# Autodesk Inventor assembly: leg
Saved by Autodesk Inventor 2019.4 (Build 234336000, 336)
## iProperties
Created: 2020-09
Part Number: leg
Document SubType Name: Assembly
Designer: Administrator
Title: leg
Author: Administrator
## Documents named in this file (5)
- c:\worker\convert-fusion-r07\tmp\job-1\164\output\files\c50c4620-2026-4653-9277-f8972be5ac5a\leg_3.iam
- c:\worker\convert-fusion-r07\tmp\job-1\164\output\files\c50c4620-2026-4653-9277-f8972be5ac5a\legA.ipt
- c:\worker\convert-fusion-r07\tmp\job-1\164\output\files\c50c4620-2026-4653-9277-f8972be5ac5a\legB.ipt
- c:\worker\convert-fusion-r07\tmp\job-1\164\output\files\c50c4620-2026-4653-9277-f8972be5ac5a\legC.ipt
- c:\worker\convert-fusion-r07\tmp\job-1\164\output\files\c50c4620-2026-4653-9277-f8972be5ac5a\legD.ipt
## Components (4 placed, 4 different names)
1. legA:1
2. legB:1
3. legC:1
4. legD:1
